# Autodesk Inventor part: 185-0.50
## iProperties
Created: 2007-06
Part Number: 185-0.50
Document SubType Name: Modeling
Designer: btaylor
Density: 1 g/cm^3
Author: btaylor
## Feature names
1. Extrusion1
2. Extrusion2
3. Extrusion3
4. Chamfer1
5. Fillet1
6. Fillet2
7. Fillet3
